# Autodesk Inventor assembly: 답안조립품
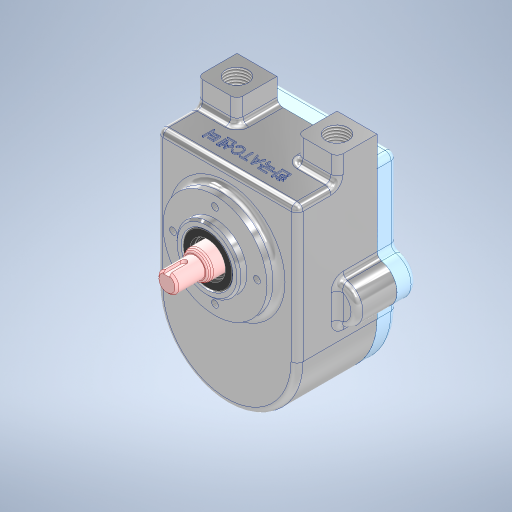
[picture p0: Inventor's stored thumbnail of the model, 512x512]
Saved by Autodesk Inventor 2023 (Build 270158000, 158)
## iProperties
Created: 2024-03
Part Number: 답안조립품
Document SubType Name: Assembly
Designer: asung
Author: asung
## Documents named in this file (8)
- C:\Users\asung\Desktop\740304V1009\답안조립품.iam
- C:\Users\asung\Desktop\740304V1009\본체.ipt
- C:\Users\asung\Desktop\740304V1009\오일레스 부시.ipt
- C:\Users\asung\Desktop\740304V1009\구동기어.ipt
- C:\Users\asung\Desktop\740304V1009\스퍼기어.ipt
- C:\Users\asung\Desktop\740304V1009\오일 실 14 25 7.ipt
- C:\Users\asung\Desktop\740304V1009\커버.ipt
- C:\Users\asung\Desktop\740304V1009\육각 소켓 머리 볼트 M5x12.ipt
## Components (1 placed, 1 different names)
1. 구동기어:1
